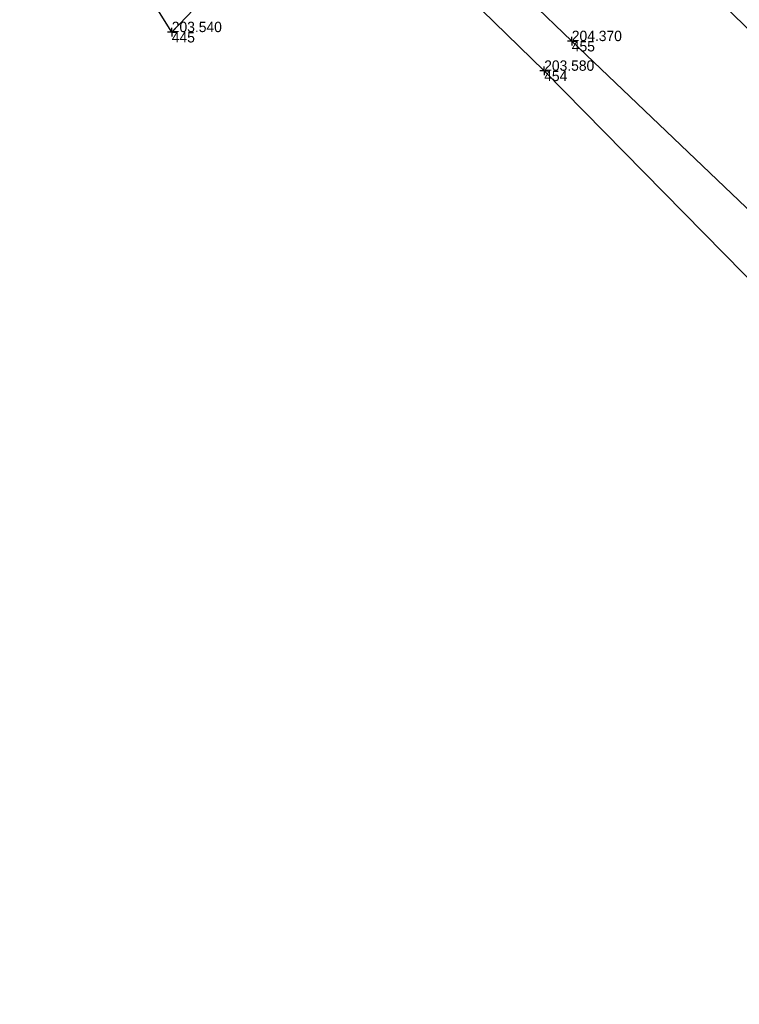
# Model space of a CAD drawing. Extents: x -744883 to -744469, y -966832 to -966374.
# Drawn here: x -744593.2 to -744551.5, y -966807.1 to -966750.1 of the extents above; entities that cross this region are included whole.
import ezdxf

# ---------------------------------------------------------------- set-up
doc = ezdxf.new("R2010")
doc.units = 0
for name, color, linetype in [('Body polohopisu', 7, 'Continuous'), ('Ploty_opěrné zdi', 7, 'Continuous'), ('Rozhraní ploch', 7, 'Continuous'), ('Výšky bodů', 7, 'Continuous'), ('Čísla bodů', 7, 'Continuous')]:
    doc.layers.add(name, color=color, linetype=linetype)

msp = doc.modelspace()

# ---------------------------------------------------------------- linework, layer by layer
at = {"layer": 'Body polohopisu'}
for p, q in [((-744584.36, -966750.78), (-744584.36, -966750.53)), ((-744584.36, -966750.78), (-744584.61, -966750.78)), ((-744584.36, -966750.78), (-744584.11, -966750.78)), ((-744584.36, -966750.78), (-744584.36, -966751.03)), ((-744561.19, -966751.3), (-744561.19, -966751.05)), ((-744561.19, -966751.3), (-744561.44, -966751.3)), ((-744561.19, -966751.3), (-744560.94, -966751.3)), ((-744561.19, -966751.3), (-744561.19, -966751.55)), ((-744562.79, -966753.02), (-744562.79, -966752.77)), ((-744562.79, -966753.02), (-744563.04, -966753.02)), ((-744562.79, -966753.02), (-744562.54, -966753.02)), ((-744562.79, -966753.02), (-744562.79, -966753.27))]:
    msp.add_line(p, q, dxfattribs=at)
at = {"layer": 'Ploty_opěrné zdi'}
for points in [[(-744584.36, -966750.78), (-744575.07, -966741.05), (-744562.79, -966753.02)], [(-744562.79, -966753.02), (-744544.29, -966771.83)]]:
    msp.add_lwpolyline(points, dxfattribs=at)
at = {"layer": 'Rozhraní ploch'}
for points in [[(-744484.45, -966802.29), (-744488.93, -966807.11), (-744494.18, -966806.31), (-744504.16, -966796.59), (-744523.84, -966777.07), (-744535.89, -966765.33), (-744540.85, -966760.58), (-744553.38, -966748.22), (-744567.31, -966735.07), (-744575.15, -966727.6), (-744592.64, -966710.64), (-744593.17, -966705.66)], [(-744584.36, -966750.78), (-744585.27, -966749.34), (-744576.16, -966739.68), (-744573.45, -966739.5), (-744561.19, -966751.3), (-744536.79, -966774.59), (-744538.25, -966777.52)]]:
    msp.add_lwpolyline(points, dxfattribs=at)

# ---------------------------------------------------------------- texts
at = {"layer": 'Výšky bodů'}
for s, p in [('203.540', (-744584.36, -966750.78)), ('204.370', (-744561.19, -966751.3)), ('203.580', (-744562.79, -966753.02))]:
    msp.add_text(s, height=0.6, dxfattribs=at).set_placement(p)
at = {"layer": 'Čísla bodů'}
for s, p in [('445', (-744584.36, -966751.38)), ('455', (-744561.19, -966751.9)), ('454', (-744562.79, -966753.62))]:
    msp.add_text(s, height=0.6, dxfattribs=at).set_placement(p)

doc.saveas('drawing.dxf')
